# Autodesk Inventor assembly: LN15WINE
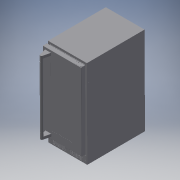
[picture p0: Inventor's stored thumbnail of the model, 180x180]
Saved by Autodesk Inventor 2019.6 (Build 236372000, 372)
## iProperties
Company: none
Created: 2025-04
Part Number: LN15WINE
Description: CATIA V5 STEP
Document SubType Name: Assembly
Designer: MMAK
Authority: none
Title: C:\Users\MMAK\Documents\SmarTeam\WEBSITE CAD\Lynx STP\LN15WINE.stp
Author: none
Sending System: CATIA V5 STEP AP203 v2
Preprocessor: CATIA Unofficial Packaging Version SP2
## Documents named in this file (4)
- C:\Users\MMAK\Documents\SmarTeam\WEBSITE CAD\Lynx STP\LN15WINE.iam
- C:\Users\MMAK\Documents\SmarTeam\WEBSITE CAD\Lynx STP\LOCL215-SS01A.iam
- C:\Users\MMAK\Documents\SmarTeam\WEBSITE CAD\Lynx STP\OC UC 15.ipt
- C:\Users\MMAK\Documents\SmarTeam\WEBSITE CAD\Lynx STP\Product90.iam
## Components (3 placed, 3 different names)
1. LOCL215-SS01A.1 [sub-assembly]
2. OC UC 15.1
3. Product90.1 [sub-assembly]
